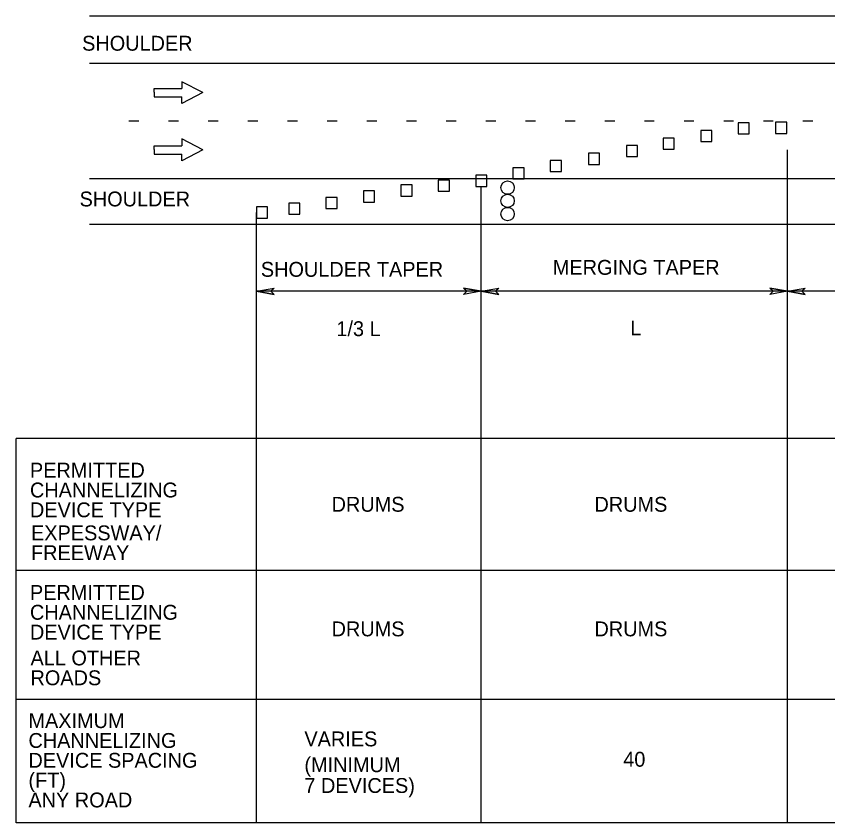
# Model space of a CAD drawing. Extents: x 12.4 to 19.6, y 4 to 16.
# Drawn here: x 12.407 to 15.682, y 8.348 to 11.602 of the extents above; entities that cross this region are included whole.
import ezdxf

# ---------------------------------------------------------------- set-up
doc = ezdxf.new("R2010")
doc.units = 0
for name, color, linetype in [('DETL-DIMS', 7, 'Continuous'), ('DETL-LINE', 7, 'Continuous'), ('DETL-NOTE', 7, 'Continuous'), ('MRKG-LINE', 7, 'Continuous'), ('USER-BORD', 7, 'Continuous')]:
    doc.layers.add(name, color=color, linetype=linetype)

# ---------------------------------------------------------------- blocks, each defined once
blk = doc.blocks.new('DIR2')
at = {"layer": 'USER-BORD'}
for p, q in [((0, 0.001), (-0.034, -0.048)), ((0, 0.001), (0.034, -0.048)), ((-0.034, -0.048), (-0.013, -0.048)), ((-0.013, -0.113), (-0.013, -0.048)), ((0.034, -0.048), (0.013, -0.048)), ((0.013, -0.113), (0.013, -0.048)), ((-0.001, -0.113), (-0.013, -0.113)), ((-0.001, -0.113), (0.001, -0.113)), ((0.001, -0.113), (0.013, -0.113))]:
    blk.add_line(p, q, dxfattribs=at)
blk = doc.blocks.new('PANEL0')
at = {"layer": 'USER-BORD'}
for centre in [(0.0309, -0.0012), (0.0928, -0.0012), (0.1546, -0.0012)]:
    blk.add_circle(centre, 0.0312, dxfattribs=at)

msp = doc.modelspace()

# ---------------------------------------------------------------- linework, layer by layer
at = {"layer": 'DETL-DIMS'}
for p, q in [((15.5201, 8.348), (15.5201, 11.0623)), ((14.284, 8.348), (14.284, 10.9135)), ((13.3764, 8.348), (13.3764, 10.8101)), ((13.3764, 10.4922), (13.4479, 10.5048)), ((19.0458, 10.4922), (13.3764, 10.4922)), ((13.3764, 10.4922), (13.4479, 10.4796)), ((13.4344, 10.4922), (13.4479, 10.5048)), ((13.4479, 10.4796), (13.4344, 10.4922)), ((14.284, 10.4922), (14.2125, 10.5048)), ((14.2125, 10.5048), (14.226, 10.4922)), ((14.284, 10.4922), (14.2125, 10.4796)), ((14.226, 10.4922), (14.2125, 10.4796)), ((14.284, 10.4922), (14.3555, 10.5048)), ((14.284, 10.4922), (14.3555, 10.4796)), ((14.342, 10.4922), (14.3555, 10.5048)), ((14.3555, 10.4796), (14.342, 10.4922)), ((15.5201, 10.4922), (15.4486, 10.5048)), ((15.4486, 10.5048), (15.4621, 10.4922)), ((15.5201, 10.4922), (15.4486, 10.4796)), ((15.4621, 10.4922), (15.4486, 10.4796)), ((15.5201, 10.4922), (15.5916, 10.5048)), ((15.5201, 10.4922), (15.5916, 10.4796)), ((15.5781, 10.4922), (15.5916, 10.5048)), ((15.5916, 10.4796), (15.5781, 10.4922)), ((19.0458, 9.8978), (12.4073, 9.8978)), ((12.4073, 8.348), (12.4073, 9.8978)), ((19.0458, 9.3657), (12.4073, 9.3657)), ((19.0458, 8.8452), (12.4073, 8.8452)), ((19.0458, 8.348), (12.4073, 8.348))]:
    msp.add_line(p, q, dxfattribs=at)
for points in [[(13.4479, 10.4796), (13.3764, 10.4922), (13.4479, 10.5048), (13.4344, 10.4922)], [(14.2125, 10.5048), (14.284, 10.4922), (14.2125, 10.4796), (14.226, 10.4922)], [(14.3555, 10.4796), (14.284, 10.4922), (14.3555, 10.5048), (14.342, 10.4922)], [(15.4486, 10.5048), (15.5201, 10.4922), (15.4486, 10.4796), (15.4621, 10.4922)], [(15.5916, 10.4796), (15.5201, 10.4922), (15.5916, 10.5048), (15.5781, 10.4922)]]:
    msp.add_lwpolyline(points, close=True, dxfattribs=at)
at = {"layer": 'MRKG-LINE'}
for p, q in [((19.5024, 11.6019), (12.7024, 11.6019)), ((19.5024, 11.411), (12.7024, 11.411)), ((12.9024, 11.1781), (12.8624, 11.1781)), ((13.0624, 11.1781), (13.0224, 11.1781)), ((13.2224, 11.1781), (13.1824, 11.1781)), ((13.3824, 11.1781), (13.3424, 11.1781)), ((13.5424, 11.1781), (13.5024, 11.1781)), ((13.7024, 11.1781), (13.6624, 11.1781)), ((13.8624, 11.1781), (13.8224, 11.1781)), ((14.0224, 11.1781), (13.9824, 11.1781)), ((14.1824, 11.1781), (14.1424, 11.1781)), ((14.3424, 11.1781), (14.3024, 11.1781)), ((14.5024, 11.1781), (14.4624, 11.1781)), ((14.6624, 11.1781), (14.6224, 11.1781)), ((14.8224, 11.1781), (14.7824, 11.1781)), ((14.9824, 11.1781), (14.9424, 11.1781)), ((15.1424, 11.1781), (15.1024, 11.1781)), ((15.3024, 11.1781), (15.2624, 11.1781)), ((15.4624, 11.1781), (15.4224, 11.1781)), ((15.6224, 11.1781), (15.5824, 11.1781)), ((19.5024, 10.9461), (12.7024, 10.9461)), ((19.5024, 10.7623), (12.7024, 10.7623))]:
    msp.add_line(p, q, dxfattribs=at)
for points in [[(15.3204, 11.1716), (15.3204, 11.1268), (15.3652, 11.1268), (15.3652, 11.1716)], [(15.4721, 11.1741), (15.4721, 11.1293), (15.5169, 11.1293), (15.5169, 11.1741)], [(15.1701, 11.141), (15.1701, 11.0962), (15.2149, 11.0962), (15.2149, 11.141)], [(15.0183, 11.1103), (15.0183, 11.0655), (15.0631, 11.0655), (15.0631, 11.1103)], [(14.8697, 11.0808), (14.8697, 11.036), (14.9145, 11.036), (14.9145, 11.0808)], [(14.7163, 11.0491), (14.7163, 11.0043), (14.7611, 11.0043), (14.7611, 11.0491)], [(14.5624, 11.0198), (14.5624, 10.975), (14.6072, 10.975), (14.6072, 11.0198)], [(14.4121, 10.9906), (14.4121, 10.9458), (14.4569, 10.9458), (14.4569, 10.9906)], [(14.1104, 10.9408), (14.1104, 10.896), (14.1552, 10.896), (14.1552, 10.9408)], [(14.2621, 10.9602), (14.2621, 10.9154), (14.3069, 10.9154), (14.3069, 10.9602)], [(13.96, 10.9213), (13.96, 10.8765), (14.0048, 10.8765), (14.0048, 10.9213)], [(13.8088, 10.897), (13.8088, 10.8522), (13.8536, 10.8522), (13.8536, 10.897)], [(13.5074, 10.8483), (13.5074, 10.8035), (13.5522, 10.8035), (13.5522, 10.8483)], [(13.6571, 10.8706), (13.6571, 10.8258), (13.7019, 10.8258), (13.7019, 10.8706)], [(13.3764, 10.8325), (13.3764, 10.7877), (13.4212, 10.7877), (13.4212, 10.8325)]]:
    msp.add_lwpolyline(points, close=True, dxfattribs=at)

# ---------------------------------------------------------------- block references
at = {"layer": 'DETL-LINE', "rotation": -90.00000000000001}
for name, p, xscale, yscale in [('DIR2', (13.1588, 11.2937), 1.2917647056, 1.7223529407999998), ('DIR2', (13.1588, 11.0627), 1.2917647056, 1.7223529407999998), ('PANEL0', (14.3915, 10.937), 0.8611764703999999, 0.8611764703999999)]:
    msp.add_blockref(name, p, dxfattribs=dict(at, xscale=xscale, yscale=yscale))

# ---------------------------------------------------------------- texts
at = {"layer": 'DETL-NOTE'}
for s, p in [('SHOULDER', (12.6732, 11.4629)), ('SHOULDER', (12.663, 10.8346)), ('SHOULDER TAPER', (13.3945, 10.5507)), ('MERGING TAPER', (14.5729, 10.5587)), ('1/3 L', (13.6994, 10.3112)), ('L', (14.8854, 10.3141)), ('PERMITTED ', (12.4627, 9.7405)), ('CHANNELIZING', (12.4627, 9.6605)), ('DEVICE TYPE', (12.4627, 9.5805)), ('EXPESSWAY/', (12.467, 9.4875)), ('FREEWAY', (12.467, 9.4075)), ('PERMITTED ', (12.4627, 9.2472)), ('CHANNELIZING ', (12.4627, 9.1672)), ('DEVICE TYPE', (12.4627, 9.0872)), ('ALL OTHER ', (12.4649, 8.9829)), ('ROADS', (12.4649, 8.9029)), ('MAXIMUM ', (12.4566, 8.73)), ('VARIES', (13.5703, 8.6563)), ('CHANNELIZING ', (12.4566, 8.65)), ('DEVICE SPACING', (12.4566, 8.57)), ('(MINIMUM', (13.5703, 8.5523)), ('40', (14.8571, 8.5742)), ('(FT)', (12.4566, 8.49)), ('7 DEVICES)', (13.5703, 8.4683)), ('ANY ROAD', (12.4566, 8.41))]:
    msp.add_text(s, height=0.06, rotation=360, dxfattribs=at).set_placement(p)
for p in [(13.6801, 9.6028), (14.7409, 9.6028), (13.6801, 9.1002), (14.7409, 9.1002)]:
    msp.add_text('DRUMS ', height=0.06, dxfattribs=at).set_placement(p)

doc.saveas('drawing.dxf')
